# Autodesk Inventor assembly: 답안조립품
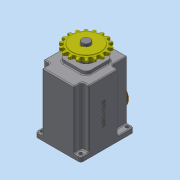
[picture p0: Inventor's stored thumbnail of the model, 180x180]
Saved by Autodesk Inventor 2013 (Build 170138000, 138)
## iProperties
Created: 2017-12
Part Number: 답안조립품
Document SubType Name: Assembly
Designer: dgall
Mass: 1781.55 g
Surface Area: 2015.55 cm^2
Volume: 734.127 cm^3
Density: 2.42676 g/cm^3
Author: dgall
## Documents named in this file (17)
- C:\Users\dgall\Desktop\371207V1007\답안조립품.iam
- C:\Users\dgall\Desktop\371207V1007\본체.ipt
- C:\Users\dgall\Desktop\371207V1007\메인축.ipt
- C:\Users\dgall\Desktop\371207V1007\서브축.ipt
- C:\Users\dgall\Desktop\371207V1007\키 5 x 5 x 18.ipt
- C:\Users\dgall\Desktop\371207V1007\멈춤나사 M3x8.ipt
- C:\Users\dgall\Desktop\371207V1007\스프로킷.ipt
- C:\Users\dgall\Desktop\371207V1007\베어링 6003.ipt
- C:\Users\dgall\Desktop\371207V1007\베어링 608.ipt
- C:\Users\dgall\Desktop\371207V1007\커버.ipt
- C:\Users\dgall\Desktop\371207V1007\오일 실 17 32 8.ipt
- C:\Users\dgall\Desktop\371207V1007\오일 실 8 22 7.ipt
- C:\Users\dgall\Desktop\371207V1007\슬라이더.ipt
- C:\Users\dgall\Desktop\371207V1007\부시.ipt
- C:\Users\dgall\Desktop\371207V1007\가변스프링.ipt
- C:\Users\dgall\Desktop\371207V1007\상부 캡.ipt
- C:\Users\dgall\Desktop\371207V1007\볼트 M4 x 10.ipt
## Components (1 placed, 1 different names)
1. 가변스프링:1
